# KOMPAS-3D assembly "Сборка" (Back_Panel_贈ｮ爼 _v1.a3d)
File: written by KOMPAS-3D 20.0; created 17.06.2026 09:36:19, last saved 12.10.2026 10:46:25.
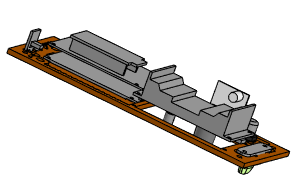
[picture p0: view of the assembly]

Document properties: Полное имя файла: D:\RicWork\Project-EPS32\box_compas\Back_Panel_Сборка_v1.a3d

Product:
- Part/product: Сборка
    Масса: 0.615753
  - Component [detail]: Деталь  | Масса: 0.0197779; source file: USB-C_Type-C.m3d
  - Component [detail]: Деталь  | Масса: 0.0193926; source file: KCD1.m3d
  - Component [detail]: Деталь  | Материал: Полипропилен  ГОСТ 26996-86 (density 900 kg/m3); Масса: 0.00646155; source file: ns4248.m3d
  - Component [detail]: Деталь  | Материал: Фторопласт-4  ГОСТ 10007-80 Е (density 2200 kg/m3); Масса: 0.00400772; source file: TZT_EC11.m3d
  - Component [detail]: Деталь  | Масса: 0.213936; source file: chip.m3d
  - Component [detail]: Деталь  | Материал: Фанера, береза,ФСФ ВВ/С ГОСТ 3916.1-2018 (density 760 kg/m3); Масса: 0.0226889; source file: back_panel_v2.m3d
  - Component [detail]: Деталь  | Масса: 0.00471805; source file: HX1838.m3d
  - Component [detail]: Деталь  | Масса: 0.324771; source file: ups.m3d

Referenced files in D:\RicWork\Project-EPS32\box_compas\: back_panel_v2.m3d, chip.m3d, TZT_EC11.m3d, ns4248.m3d, KCD1.m3d, USB-C_Type-C.m3d, HX1838.m3d, ups.m3d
